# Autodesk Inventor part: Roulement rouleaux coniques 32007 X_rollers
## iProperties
Created: 2000-12
Part Number: Roulement rouleaux coniques 32007 X_rollers
Material: Par défaut
Document SubType Name: Modélisation
Designer: Administrateur
Control State: 0
Master: False
Checked Out: False
Shininess: 20.0
Length Units: 11269
Angle Units: 11279
Time Units: 11290
Mass Units: 11283
Length Display Precision: 3
Angle Display Precision: 2
Density: 0.0
Volumn: 0.0
Area: 0.0
PropertySet Name: Model Information
Author: Administrateur
